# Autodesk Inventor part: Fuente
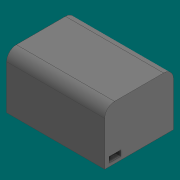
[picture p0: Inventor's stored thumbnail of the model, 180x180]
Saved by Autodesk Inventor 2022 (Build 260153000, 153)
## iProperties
Created: 2021-11
Part Number: Fuente
Material: Generic
Document SubType Name: Modeling
Designer: santi
Density: 1 g/cm^3
Appearance: Default
Author: santi
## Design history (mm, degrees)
sketch "Sketch1"
  geometry: L1 (0, 0)-(0, -28); L2 (0, -28)-(40, -28); L3 (40, -28)-(40, 0); L4 (40, 0)-(0, 0)
  constraints: 8 end point, 3 perpendicular, 1 vertical
  dimensions: "d0" = 28 distance of L1.start L1.end; "d1" = 40 distance of L1.end L2.end
extrude "Extrusion1" new body sketch "Sketch1" distance "d2" = 22; taper "d3" = 0 deg
fillet "Fillet1" dims "d4" = 4
sketch "Sketch2"
  geometry: L1 (1.789, 1.346)-(6.549, 1.346); L2 (6.549, 1.346)-(6.549, 3.611); L3 (6.549, 3.611)-(1.789, 3.611); L4 (1.789, 3.611)-(1.789, 1.346); 1 further point
  constraints: 8 end point, 2 parallel, 1 horizontal, 1 perpendicular
extrude "Extrusion2" cut sketch "Sketch2" distance "d5" = 2; taper "d6" = 0 deg
sketch "Sketch3"
  geometry: L1 (1.954, 1.49)-(6.875, 1.49); L2 (6.875, 1.49)-(6.875, 3.753); L3 (6.875, 3.753)-(1.954, 3.753); L4 (1.954, 3.753)-(1.954, 1.49); 1 further point
  constraints: 8 end point, 2 parallel, 1 horizontal, 1 perpendicular
extrude "Extrusion3" cut sketch "Sketch3" distance "d7" = 2; taper "d8" = 0 deg
body "Solid1"
